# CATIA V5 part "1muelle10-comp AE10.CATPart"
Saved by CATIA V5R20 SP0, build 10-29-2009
Part number: 1muelle10-comp AE10
Revision: ANY
Definition: UNKNOWN
Nomenclature: 1muelle10-comp AE10
Source: Unknown
Bounding box of the stored display mesh (mm): x -6.75 to 6.75, y -6.75 to 6.75, z -0.001 to 8.349
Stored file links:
  C:\Users\Utente\Desktop\IO LAVORO\3D X SITO CF\CUMSA\3D files BA\BA 101822\1muelle10-comp AE10.CATPart
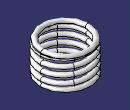
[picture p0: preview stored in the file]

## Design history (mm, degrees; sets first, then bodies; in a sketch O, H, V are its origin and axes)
Set1 "FacciaKO#NONE#1443"
  DatumSurface1 "Sup1443_1"
  DatumCurve1 "Crv1443_1"
Set2 "FacciaKO#NONE#1434"
  DatumSurface2 "Sup1434_1"
  DatumCurve2 "Crv1434_1"
Body1 "Cortar-Extruir1" (main body)
  Solid1: solid without history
